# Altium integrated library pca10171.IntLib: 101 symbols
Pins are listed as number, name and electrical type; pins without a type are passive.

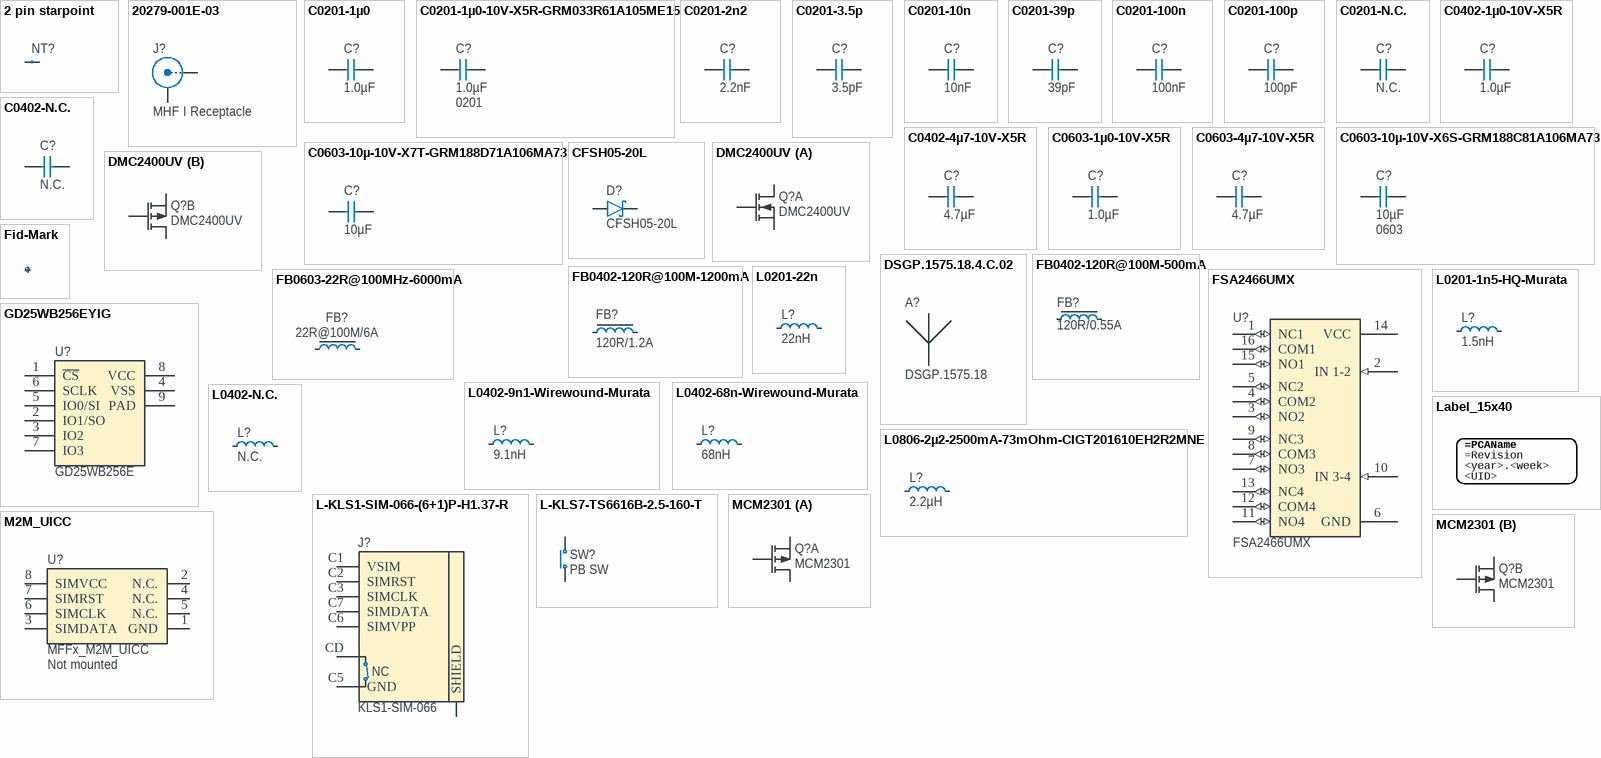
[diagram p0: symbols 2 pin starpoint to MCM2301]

## 2 pin starpoint
designator NT?, comment Net tie  (value not drawn)  (net tie, no BOM)
Starpoint; Part Number: 2 pin starpoint; Manufacturer: N.A.; Part number NEMS: 100500603; Pad Count: 2; Component Status: Active; System: Connector
footprint 2 PIN STARPOINT
pins: 1, 2

## 20279-001E-03
designator J?, comment MHF I Receptacle
Ultraminiature Coaxial Connector, 50 Ohm, SMD; Part Number: 20279-001E-03; Manufacturer: Wellshow; Part number IPS: 00000004436; Part number NEMS: 100500636; Note: N.A.; Pad Count: 3; Component Status: Active
footprint COAXIAL RF U.FL-R-SMT-1
pins: 1 X, 2 Y

## C0201-1µ0
designator C?, comment 1.0µF
Capacitor, X5R, ±10%; Part Number: C0201-1µ0; Manufacturer: N.A.; Part number IPS: 00000001723; Part number NEMS: 100200084; Note: 10V; Pad Count: 2; Component Status: Active
footprint CAPC0603X03L_C
pins: 1, 2

## C0201-1µ0-10V-X5R-GRM033R61A105ME15
designator C?, comment 1.0µF  Footprint Doc: 0201
Capacitor, X5R, ±20%, 10V; Part Number: C0201-1µ0-10V-X5R-GRM033R61A105ME15; Manufacturer: Murata; Manufacturer Part Number: GRM033R61A105ME15; Part number NEMS: 100200545; Artikkelnr Noca: N.A.; Pad Count: 2; Component Status: Active
footprint CAPC0603X03L_C
pins: 1, 2

## C0201-2n2
designator C?, comment 2.2nF
Capacitor, X7R, ±10%, 10V; Part Number: C0201-2n2; Manufacturer: N.A.; Part number IPS: 00000001778; Part number Norautron: 26470002; Part number NEMS: 100200060; Pad Count: 2; Component Status: Active
footprint CAPC0603X03L_C
pins: 1, 2

## C0201-3.5p
designator C?, comment 3.5pF
Capacitor, NP0, ±0.1pF, 25V; Part Number: C0201-3.5p; Manufacturer: Murata; Manufacturer Part Number: GJM0335C1H3R5BB01E; Part number IPS: 00000001469; Part number NEMS: 100200023; Artikkelnr Noca: N.A.; Pad Count: 2; Component Status: Active
footprint CAPC0603X03L_C
pins: 1, 2

## C0201-10n
designator C?, comment 10nF
Capacitor, X7R, ±10%; Part Number: C0201-10n; Manufacturer: N.A.; Part number IPS: 00000003480; Part number Norautron: 26621779; Part number NEMS: 100200067; Note: 10V; Pad Count: 2; Component Status: Active
footprint CAPC0603X03L_C
pins: 1, 2

## C0201-39p
designator C?, comment 39pF
Capacitor, NP0, ±1%, 25V; Part Number: C0201-39p; Manufacturer: Murata; Manufacturer Part Number: GRM0335C1E390FA01; Part number IPS: 00000001668; Part number NEMS: 100200039; Artikkelnr Noca: N.A.; Pad Count: 2; Component Status: Active
footprint CAPC0603X03L_C
pins: 1, 2

## C0201-100n
designator C?, comment 100nF
Capacitor, X5R, ±10%; Part Number: C0201-100n; Manufacturer: N.A.; Part number IPS: 00000001248, 00000002505; Part number Norautron: 262071862; Part number NEMS: 100200078; Note: 16V; Pad Count: 2; Component Status: Active
footprint CAPC0603X03L_C
pins: 1, 2

## C0201-100p
designator C?, comment 100pF
Capacitor, NP0, ±2%, 25V; Part Number: C0201-100p; Manufacturer: Murata; Manufacturer Part Number: GRM0335C1E101GA01; Part number IPS: 00000007853; Part number NEMS: 100200044; Artikkelnr Noca: N.A.; Pad Count: 2; Component Status: Active
footprint CAPC0603X03L_C
pins: 1, 2

## C0201-N.C.
designator C?, comment N.C.
Not mounted; Part Number: C0201-N.C.; Manufacturer: N.A.; Part number NEMS: 100200001; Note: Chip Cap; Assembly: Not mounted; Pad Count: 2; Component Status: Active
footprint CAPC0603X03L_C_NC
pins: 1, 2

## C0402-1µ0-10V-X5R
designator C?, comment 1.0µF
Capacitor, Ceramic, X5R, ±10%, 10V; Part Number: C0402-1µ0-10V-X5R; Manufacturer: N.A.; Part number NEMS: 100200482; Pad Count: 2; Component Status: Active
footprint CAPC1005X04L
pins: 1, 2

## C0402-4µ7-10V-X5R
designator C?, comment 4.7µF
Capacitor, X5R, 10V; Part Number: C0402-4µ7-10V-X5R; Manufacturer: Murata; Manufacturer Part Number: GRM155R61A475MEAAD; Part number NEMS: 100200415; Artikkelnr Noca: N.A.; Pad Count: 2; Component Status: Active
footprint CAPC1005X04L
pins: 1, 2

## C0402-N.C.
designator C?, comment N.C.
Not mounted; Part Number: C0402-N.C.; Manufacturer: N.A.; Part number NEMS: 100200105; Assembly: Not mounted; Note: Chip Cap; Pad Count: 2; Component Status: Active
footprint CAPC1005X04L_NC
pins: 1, 2

## C0603-1µ0-10V-X5R
designator C?, comment 1.0µF
Capacitor, Ceramic, 1.0µF 10V X5R 0603,±10%; Part Number: C0603-1µ0-10V-X5R; Manufacturer: N.A.; Part number NEMS: 100200528; Component Status: Active; Pad Count: 2
footprint CAPC1608X06L
pins: 1, 2

## C0603-4µ7-10V-X5R
designator C?, comment 4.7µF
Capacitor, Ceramic, X5R, ±10%, 10V; Part Number: C0603-4µ7-10V-X5R; Manufacturer: N.A.; Part number Norautron: 262081761; Part number NEMS: 100200479; Pad Count: 2; Component Status: Active
footprint CAPC1608X06L
pins: 1, 2

## C0603-10µ-10V-X6S-GRM188C81A106MA73
designator C?, comment 10µF  Footprint Doc: 0603
Capacitor, Ceramic, 10µF 10V X6S 0603,±20%; Part Number: C0603-10µ-10V-X6S-GRM188C81A106MA73; Manufacturer: Murata; Manufacturer Part Number: GRM188C81A106MA73; Part number NEMS: 100200520; Component Status: Active; Pad Count: 2; Artikkelnr Noca: N.A.
footprint CAPC1608X06L
pins: 1, 2

## C0603-10µ-10V-X7T-GRM188D71A106MA73
designator C?, comment 10µF
Capacitor, X7T, ±20%, 10V; Part Number: C0603-10µ-10V-X7T-GRM188D71A106MA73; Manufacturer: Murata; Manufacturer Part Number: GRM188D71A106MA73; Part number IPS: 00000004696; Part number NEMS: 100200414; Component Status: Active; Pad Count: 2; Note: 10VDC; Artikkelnr Noca: N.A.
footprint CAPC1608X06L
pins: 1, 2

## CFSH05-20L
designator D?
DIODE SCHOTTKY 20V 500MA SOD882; Manufacturer: Central Semiconductor Corp.; Part number IPS: 00000002493; Part number NEMS: 101300101; Note: N.A.; Pad Count: 2; Component Status: Active
footprint SODFL35X40-2N
pins: 1 A, 3 C

## DMC2400UV
designator Q?
Dual N & P Ch MOFET, 1.03A/0.7A, 480mOhm, 450mW; Manufacturer: Diodes Incorporated; Part number IPS: 00000007803; Part number NEMS: 101300117; Note: Dual N & P Channel Digital FET; Artikkelnr Noca: N.A.; Pad Count: 6; Component Status: Active
footprint SOTFL50P162X60-6N
part A pins: 1 S1, 2 G1, 6 D1
part B pins: 3 D2, 4 S2, 5 G2

## DSGP.1575.18.4.C.02
designator A?, comment DSGP.1575.18
18 x 18 mm Low Profile GPS L1 / GALILEO E1 Passive Patch Antenna; Part Number: DSGP.1575.18.4.C.02; Manufacturer: Taoglas; Part number IPS: 00000007687; Part number NEMS: 100700073; Note: N.A.; Pad Count: 2; Component Status: Active
footprint DSGP.1575.18.4.C.02
pins: 1, 2 GND (power) hidden to GND

## FB0402-120R@100M-500mA
designator FB?, comment 120R/0.55A
Ferrite Bead, 120 Ohm @ 100MHz, 500mA, 250 mOhm Max; Part Number: FB0402-120R@100M-500mA; Manufacturer: Murata; Manufacturer Part Number: BLM15AG121SN1D; Part number IPS: 00000009954; Part number Norautron: 265230631; Part number NEMS: 100300099; Note: Chip EMIFIL Inductor Type Chip Ferrite Bead; Artikkelnr Noca: 33029317; Pad Count: 2; Component Status: Active
footprint INDC1005X04L
pins: 1, 2

## FB0402-120R@100M-1200mA
designator FB?, comment 120R/1.2A
Ferrite Bead, 120 Ohm @ 100MHz, 1200mA, 75 mOhm Max; Part Number: FB0402-120R@100M-1200mA; Manufacturer: Murata; Manufacturer Part Number: BLM15EX121SN1; Part number NEMS: 100300416; Component Status: Active; Pad Count: 2; Note: N.A.
footprint INDC1005X04L
pins: 1, 2

## FB0603-22R@100MHz-6000mA
designator FB?, comment 22R@100M/6A
Ferrite Bead, 22 Ohm @ 100MHz, 6000mA, 8 mOhm Max; Part Number: FB0603-22R@100MHz-6000mA; Manufacturer: Murata; Manufacturer Part Number: BLM18SD220SN1D; Component Status: Active; Pad Count: 2; Note: Chip EMIFIL Inductor Type Chip Ferrite Bead; Artikkelnr Noca: N.A.
footprint INDC1608X06L
pins: 1, 2

## Fid-Mark
designator Fid?, comment Fiducial mark  (value not drawn)  (no BOM)
Part Number: Fid-Mark; Manufacturer: N.A.; Part number NEMS: 100500073; Value: N.A.; Assembly: Not mounted; Pad Count: 1; Component Status: Active; System: Connector
footprint Fiducial

## FSA2466UMX
designator U?
Data / Audio Low-Voltage Dual DPDT Analog Switch; Manufacturer: ON Semiconductor; Part number IPS: 00000009986; Part number Norautron: 26500608; Part number NEMS: 101900422; Note: N.A.; Artikkelnr Noca: 15070069; Pad Count: 16; Component Status: Active
footprint XQFN40P180X260X50-16N
pins: 1 NC1 (io), 2 IN 1-2 (in), 3 NO2 (io), 4 COM2 (io), 5 NC2 (io), 6 GND (power), 7 NO3 (io), 8 COM3 (io), 9 NC3 (io), 10 IN 3-4 (in), 11 NO4 (io), 12 COM4 (io), 13 NC4 (io), 14 VCC (power), 15 NO1 (io), 16 COM1 (io)
1 alternate drawing of the same symbol

## GD25WB256EYIG
designator U?, comment GD25WB256E
Quad Serial Flash, 256Mbit, 104MHz, 1.65V - 3.6V; Part Number: GD25WB256EYIG; Manufacturer: GigaDevice; Part number NEMS: 101900774; Note: N.A.; Pad Count: 8; Component Status: Active
footprint SON127P800X80_HS-9N
pins: 1 ~{CS}, 2 IO1/SO, 3 IO2, 4 VSS, 5 IO0/SI, 6 SCLK, 7 IO3, 8 VCC, 9 PAD

## L0201-1n5-HQ-Murata
designator L?, comment 1.5nH
Inductor, 1000mA, ±0.1ｎH, 50mOhm; Part Number: L0201-1n5-HQ-Murata; Manufacturer: Murata; Manufacturer Part Number: LQP03HQ1N5B02; Part number NEMS: 100300202; Note: -55°C ~ 125°C; Artikkelnr Noca: N.A.; Pad Count: 2; Component Status: Active
footprint INDC0603X03L_C
pins: 1, 2

## L0201-22n
designator L?, comment 22nH
Chip Inductor; Part Number: L0201-22n; Manufacturer: N.A.; Part number IPS: 00000001478; Part number NEMS: 100300034; Note: High frequency chip inductor ±10%; Pad Count: 2; Component Status: Active
footprint INDC0603X03L_C
pins: 1, 2

## L0402-9n1-Wirewound-Murata
designator L?, comment 9.1nH
Inductor, 540mA, ±2%, 140mΩ, Q=25; Part Number: L0402-9n1-Wirewound-Murata; Manufacturer: Murata; Manufacturer Part Number: LQW15AN9N1G00; Part number IPS: 00000002497; Part number NEMS: 100300357; Note: -55°C ~ 125°C; Artikkelnr Noca: N.A.; Pad Count: 2; Component Status: Active
footprint INDC1005X04L_WW
pins: 1, 2

## L0402-68n-Wirewound-Murata
designator L?, comment 68nH
Inductor, 140mA, ±2%, 1960mΩ, Q=20; Part Number: L0402-68n-Wirewound-Murata; Manufacturer: Murata; Manufacturer Part Number: LQW15AN68NG00; Part number IPS: 00000002494; Part number NEMS: 100300389; Note: -55°C ~ 125°C; Artikkelnr Noca: N.A.; Pad Count: 2; Component Status: Active
footprint INDC1005X04L_WW
pins: 1, 2

## L0402-N.C.
designator L?, comment N.C.
Not mounted; Part Number: L0402-N.C.; Manufacturer: N.A.; Part number NEMS: 100300037; Assembly: Not mounted; Pad Count: 2; Component Status: Active
footprint INDC1005X04L_NC
pins: 1, 2

## L0806-2µ2-2500mA-73mOhm-CIGT201610EH2R2MNE
designator L?, comment 2.2µH
Inductor, Irms=2.5A, Isat=2.9A, ±20%, DCR=73mΩ; Part Number: L0806-2µ2-2500mA-73mOhm-CIGT201610EH2R2MNE; Manufacturer: Samsung Electro-Mechanics America; Manufacturer Part Number: CIGT201610EH2R2MNE; Part number Norautron: 26521789; Part number NEMS: 100300400; Component Status: Active; Pad Count: 2; Note: Unshielded Thin Film Inductor; Artikkelnr Noca: N.A.
footprint INDC2016X10N
pins: 1, 2

## L-KLS1-SIM-066-(6+1)P-H1.37-R
designator J?, comment KLS1-SIM-066
Nano SIM Card Connector, Push-Push, 6-Pin, H1.37mm, with CD Pin; Part Number: L-KLS1-SIM-066-(6+1)P-H1.37-R; Manufacturer: KLS Electronic; Part number NEMS: 100500776; Note: N.A.; Pad Count: 7; Component Status: Active
footprint KLS1-SIM-066
pins: 0 SHIELD (power), C1 VSIM, C2 SIMRST, C3 SIMCLK, C5 GND, C6 SIMVPP, C7 SIMDATA, CD

## L-KLS7-TS6616B-2.5-160-T
designator SW?, comment PB SW
Tactile Switch, SPNO, SMD, 160gf, 6.2x6.4x2.5mm; Part Number: L-KLS7-TS6616B-2.5-160-T; Manufacturer: KLS; Part number NEMS: 101500133, 101500001; Note: N.A.; Pad Count: 4; Component Status: Active
footprint L-KLS7-TS6616B-2.5-160-T
pins: 1 N.O, 2 COM

## Label_15x40
designator LABEL?, comment 15x40mm  (value not drawn)
PCA version label, stick-on, 15x40mm; Part Number: Label_15x40; Manufacturer: Ellco Etikett; Manufacturer Part Number: 51945; Part number NEMS: 101200030; Component Status: Active; Pad Count: 0; Note: N.A.; Assembly: Not mounted
footprint LabelSilk_15x40

## M2M_UICC
designator U?, comment MFFx_M2M_UICC  Assembly: Not mounted
M2M UICC SIM Card; Manufacturer: N.A.; Part number NEMS: 101900595; Pad Count: 8; Component Status: Active
footprint SON127P600X90_HS-8N
pins: 1 GND, 2 N.C., 3 SIMDATA, 4 N.C., 5 N.C., 6 SIMCLK, 7 SIMRST, 8 SIMVCC

## MCM2301
designator Q?
Dual P-Channel MOFET, 3.8A, 90mOhm max, 1.4W; Manufacturer: Micro Commercial Components; Part number NEMS: 101300199; Note: N.A.; Pad Count: 6; Component Status: Active
footprint DFN65P200X200X80_HS-6N
part A pins: 1 S1, 2 G1, 6 D1
part B pins: 3 D2, 4 S2, 5 G2

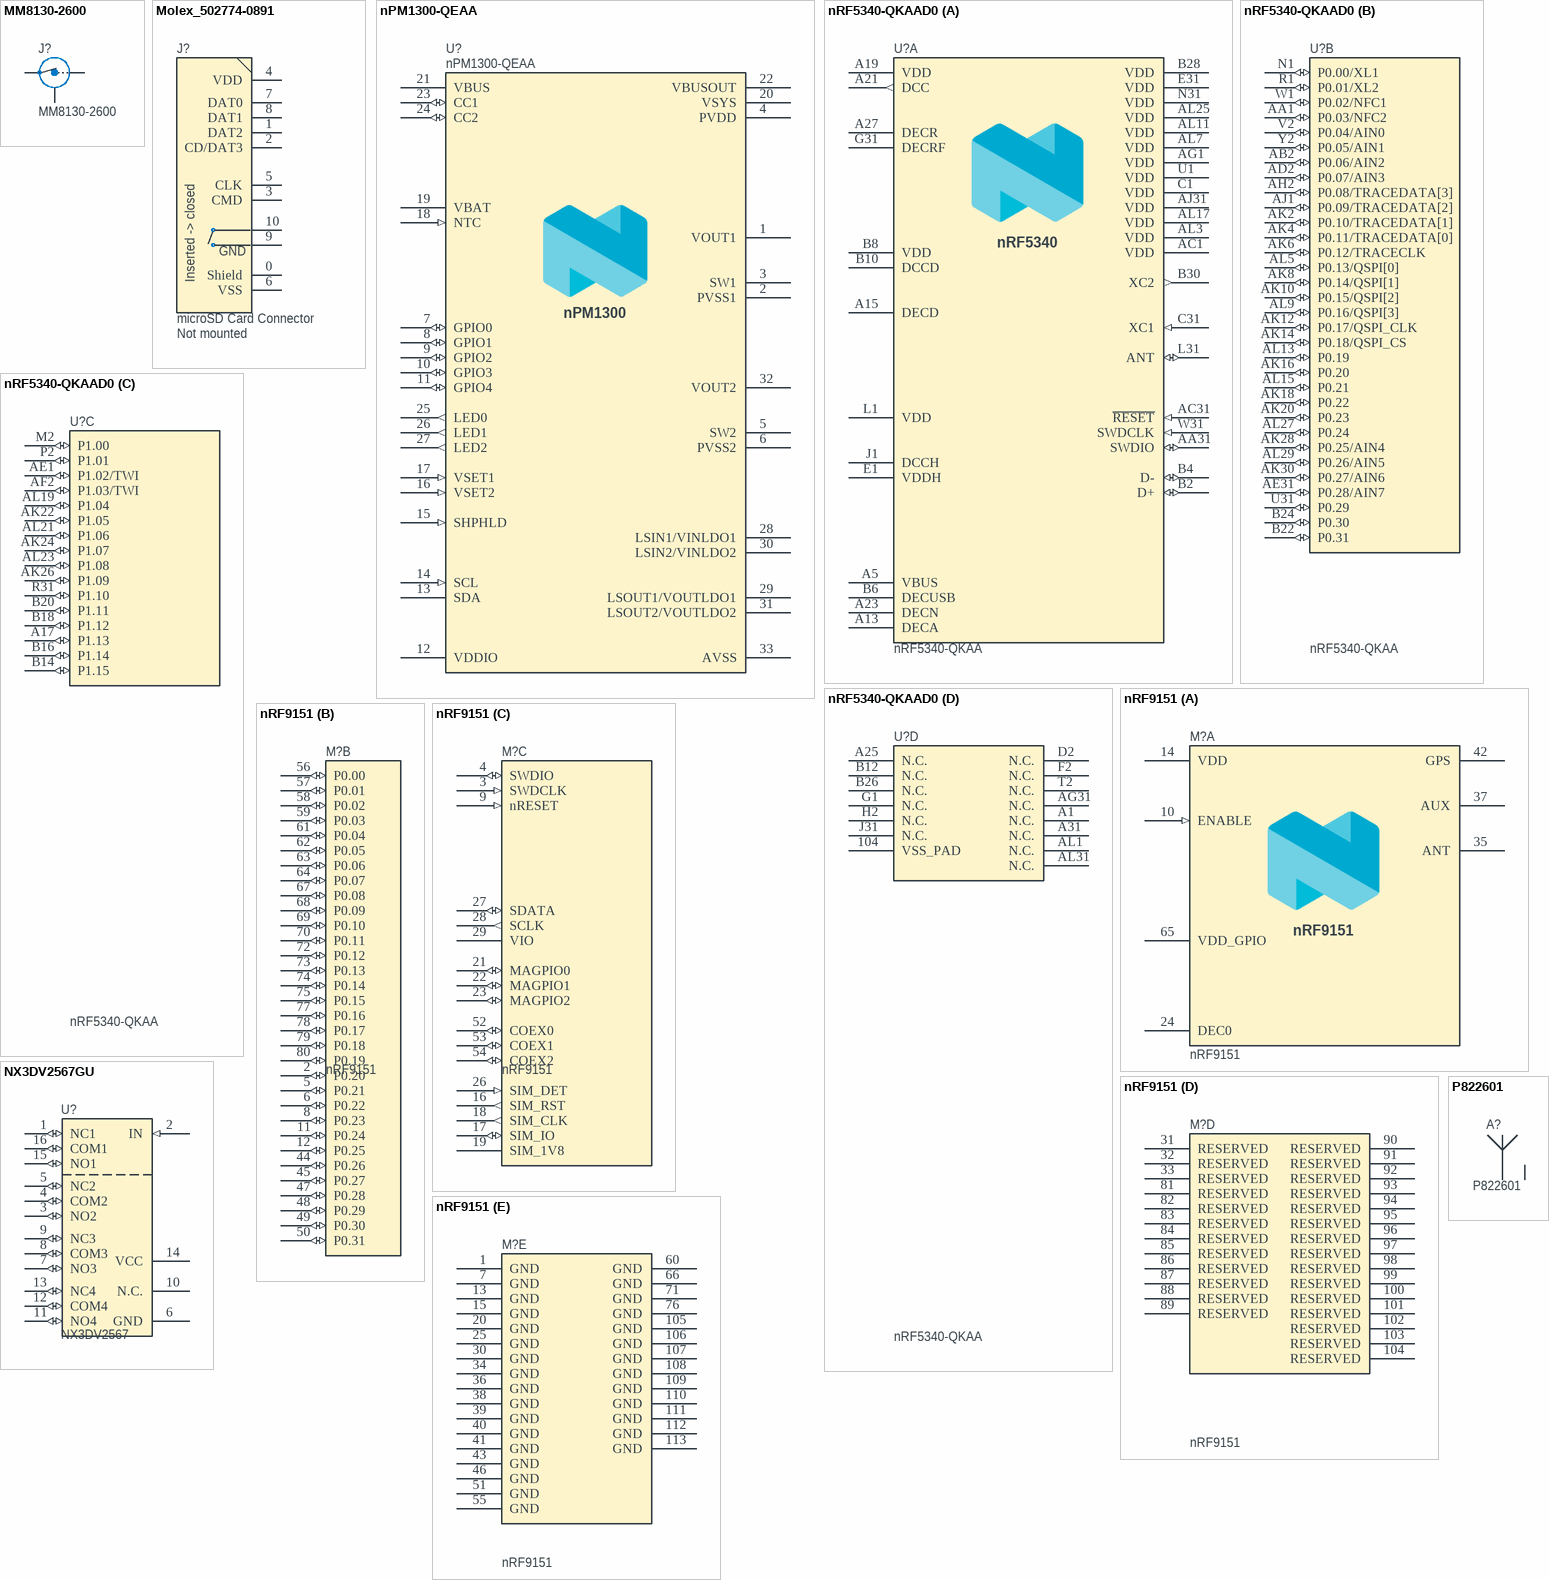
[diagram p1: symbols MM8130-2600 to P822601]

## MM8130-2600
designator J?
Coaxial Connector with Switch; Manufacturer: Murata; Part number IPS: 00000009955; Part number Norautron: 26030338; Part number NEMS: 100500400; Note: N.A.; Artikkelnr Noca: 55029011; Pad Count: 3; Component Status: Active
footprint COAXIAL-SWF
pins: 1 IN, 2 Shield, 3 OUT

## Molex_502774-0891
designator J?, comment microSD Card Connector  Assembly: Not mounted
1.10mm Pitch microSD Memory Card Connector, Reverse Mount Surface Mount, Push-Push Type; Part Number: Molex_502774-0891; Manufacturer: Molex; Manufacturer Part Number: 502774-0891; Part number IPS: 00000001284; Part number NEMS: 100500509; Note: N.A.; Pad Count: 14; Component Status: Active
footprint Molex_502774-0891
pins: 0 Shield, 1 DAT2, 2 CD/DAT3, 3 CMD, 4 VDD (power), 5 CLK, 6 VSS (power), 7 DAT0, 8 DAT1, 9, 10

## nPM1300-QEAA
designator U?
Li-Ion/Li-Polymer USB-C battery charger with high efficiency buck regulators, LDOs or load switches, LED drivers, TWI and VBUSOUT; Manufacturer: Nordic Semiconductor; Part number NEMS: 102000291; Component Status: Active; Pad Count: 33; Note: N.A.
footprint Nordic_QFN50P500X500X90-33N
pins: 1 VOUT1 (power), 2 PVSS1 (power), 3 SW1 (power), 4 PVDD (power), 5 SW2 (power), 6 PVSS2 (power), 7 GPIO0 (io), 8 GPIO1 (io), 9 GPIO2 (io), 10 GPIO3 (io), 11 GPIO4 (io), 12 VDDIO (power), 13 SDA (oc), 14 SCL (in), 15 SHPHLD (in), 16 VSET2 (in), 17 VSET1 (in), 18 NTC (in), 19 VBAT, 20 VSYS (power), 21 VBUS (power), 22 VBUSOUT (power), 23 CC1 (io), 24 CC2 (io), 25 LED0 (out), 26 LED1 (out), 27 LED2 (out), 28 LSIN1/VINLDO1 (power), 29 LSOUT1/VOUTLDO1 (power), 30 LSIN2/VINLDO2 (power), 31 LSOUT2/VOUTLDO2 (power), 32 VOUT2 (power), 33 AVSS (power)

## nRF5340-QKAAD0
designator U?, comment nRF5340-QKAA
Multi-protocol Bluetooth Low Energy, IEEE 802.15.4, ANT and 2.4GHz proprietary system-on-chip; Part Number: nRF5340-QKAAD0; Manufacturer: Nordic Semiconductor; Part number Norautron: NOD26470035; Part number NEMS: 102000216; Pad Count: 98; Note: N.A.; Component Status: Active
footprint AQFN40P700X700X85_HS-99N
part A pins: A5 VBUS (power), A13 DECA (power), A15 DECD (power), A19 VDD (power), A21 DCC (out), A23 DECN (power), A27 DECR (power), AA31 SWDIO (io), AC1 VDD (power), AC31 ~{RESET} (in), AG1 VDD (power), AJ31 VDD (power), AL3 VDD (power), AL7 VDD (power), AL11 VDD (power), AL17 VDD (power), AL25 VDD (power), B2 D+ (io), B4 D- (io), B6 DECUSB (power), B8 VDD (power), B10 DCCD (power), B28 VDD (power), B30 XC2 (out), C1 VDD (power), C31 XC1 (in), E1 VDDH (power), E31 VDD (power), G31 DECRF (power), J1 DCCH (power), L1 VDD (power), L31 ANT (io), N31 VDD (power), U1 VDD (power), W31 SWDCLK (in)
part B pins: AA1 P0.03/NFC2 (io), AB2 P0.06/AIN2 (io), AD2 P0.07/AIN3 (io), AE31 P0.28/AIN7 (io), AH2 P0.08/TRACEDATA[3] (io), AJ1 P0.09/TRACEDATA[2] (io), AK2 P0.10/TRACEDATA[1] (io), AK4 P0.11/TRACEDATA[0] (io), AK6 P0.12/TRACECLK (io), AK8 P0.14/QSPI[1] (io), AK10 P0.15/QSPI[2] (io), AK12 P0.17/QSPI_CLK (io), AK14 P0.18/QSPI_CS (io), AK16 P0.20 (io), AK18 P0.22 (io), AK20 P0.23 (io), AK28 P0.25/AIN4 (io), AK30 P0.27/AIN6 (io), AL5 P0.13/QSPI[0] (io), AL9 P0.16/QSPI[3] (io), AL13 P0.19 (io), AL15 P0.21 (io), AL27 P0.24 (io), AL29 P0.26/AIN5 (io), B22 P0.31 (io), B24 P0.30 (io), N1 P0.00/XL1 (io), R1 P0.01/XL2 (io), U31 P0.29 (io), V2 P0.04/AIN0 (io), W1 P0.02/NFC1 (io), Y2 P0.05/AIN1 (io)
part C pins: A17 P1.13 (io), AE1 P1.02/TWI (io), AF2 P1.03/TWI (io), AK22 P1.05 (io), AK24 P1.07 (io), AK26 P1.09 (io), AL19 P1.04 (io), AL21 P1.06 (io), AL23 P1.08 (io), B14 P1.15 (io), B16 P1.14 (io), B18 P1.12 (io), B20 P1.11 (io), M2 P1.00 (io), P2 P1.01 (io), R31 P1.10 (io)
part D pins: 104 VSS_PAD (power), A1 N.C., A25 N.C., A31 N.C., AG31 N.C., AL1 N.C., AL31 N.C., B12 N.C., B26 N.C., D2 N.C., F2 N.C., G1 N.C., H2 N.C., J31 N.C., T2 N.C.

## nRF9151
designator M?
Low power System-in-Package with integrated LTE-M/NB-IoT modem and GPS; Manufacturer: Nordic Semiconductor; Part number NEMS: 102000307; Component Status: Active; Pad Count: 113; Note: N.A.
footprint LGA50P1210X1110X130-113N
part A pins: 10 ENABLE (in), 14 VDD (power), 24 DEC0, 35 ANT, 37 AUX, 42 GPS, 65 VDD_GPIO (power)
part B pins: 2 P0.20 (io), 5 P0.21 (io), 6 P0.22 (io), 8 P0.23 (io), 11 P0.24 (io), 12 P0.25 (io), 44 P0.26 (io), 45 P0.27 (io), 47 P0.28 (io), 48 P0.29 (io), 49 P0.30 (io), 50 P0.31 (io), 56 P0.00 (io), 57 P0.01 (io), 58 P0.02 (io), 59 P0.03 (io), 61 P0.04 (io), 62 P0.05 (io), 63 P0.06 (io), 64 P0.07 (io), 67 P0.08 (io), 68 P0.09 (io), 69 P0.10 (io), 70 P0.11 (io), 72 P0.12 (io), 73 P0.13 (io), 74 P0.14 (io), 75 P0.15 (io), 77 P0.16 (io), 78 P0.17 (io), 79 P0.18 (io), 80 P0.19 (io)
part C pins: 3 SWDCLK (in), 4 SWDIO (io), 9 nRESET (in), 16 SIM_RST (out), 17 SIM_IO (io), 18 SIM_CLK (out), 19 SIM_1V8 (power), 21 MAGPIO0 (io), 22 MAGPIO1 (io), 23 MAGPIO2 (io), 26 SIM_DET (in), 27 SDATA (io), 28 SCLK (out), 29 VIO, 52 COEX0 (io), 53 COEX1 (io), 54 COEX2 (io)
part D pins: 31 RESERVED, 32 RESERVED, 33 RESERVED, 81 RESERVED, 82 RESERVED, 83 RESERVED, 84 RESERVED, 85 RESERVED, 86 RESERVED, 87 RESERVED, 88 RESERVED, 89 RESERVED, 90 RESERVED, 91 RESERVED, 92 RESERVED, 93 RESERVED, 94 RESERVED, 95 RESERVED, 96 RESERVED, 97 RESERVED, 98 RESERVED, 99 RESERVED, 100 RESERVED, 101 RESERVED, 102 RESERVED, 103 RESERVED, 104 RESERVED
part E pins: 1 GND, 7 GND, 13 GND, 15 GND, 20 GND, 25 GND, 30 GND, 34 GND, 36 GND, 38 GND, 39 GND, 40 GND, 41 GND, 43 GND, 46 GND, 51 GND, 55 GND, 60 GND, 66 GND, 71 GND, 76 GND, 105 GND, 106 GND, 107 GND, 108 GND, 109 GND, 110 GND, 111 GND, 112 GND, 113 GND

## NX3DV2567GU
designator U?, comment NX3DV2567
Low-ohmic four-pole double-throw analog switch; Part Number: NX3DV2567GU; Manufacturer: NXP Semiconductors; Part number IPS: 00000007816; Part number NEMS: 101900290; Note: N.A.; Artikkelnr Noca: 15079317; Pad Count: 16; Component Status: Active
footprint XQFN40P180X260X50-16N
pins: 1 NC1 (io), 2 IN (in), 3 NO2 (io), 4 COM2 (io), 5 NC2 (io), 6 GND (power), 7 NO3 (io), 8 COM3 (io), 9 NC3 (io), 10 N.C., 11 NO4 (io), 12 COM4 (io), 13 NC4 (io), 14 VCC (power), 15 NO1 (io), 16 COM1 (io)
3 alternate drawings of the same symbol

## P822601
designator A?
ANTENNA PRESTTA OCTABAND LTE; Manufacturer: Ethertronics; Part number IPS: 00000009001; Part number NEMS: 100700043; Note: N.A.; Pad Count: 2; Component Status: Active
footprint P822601
pins: 1, 2

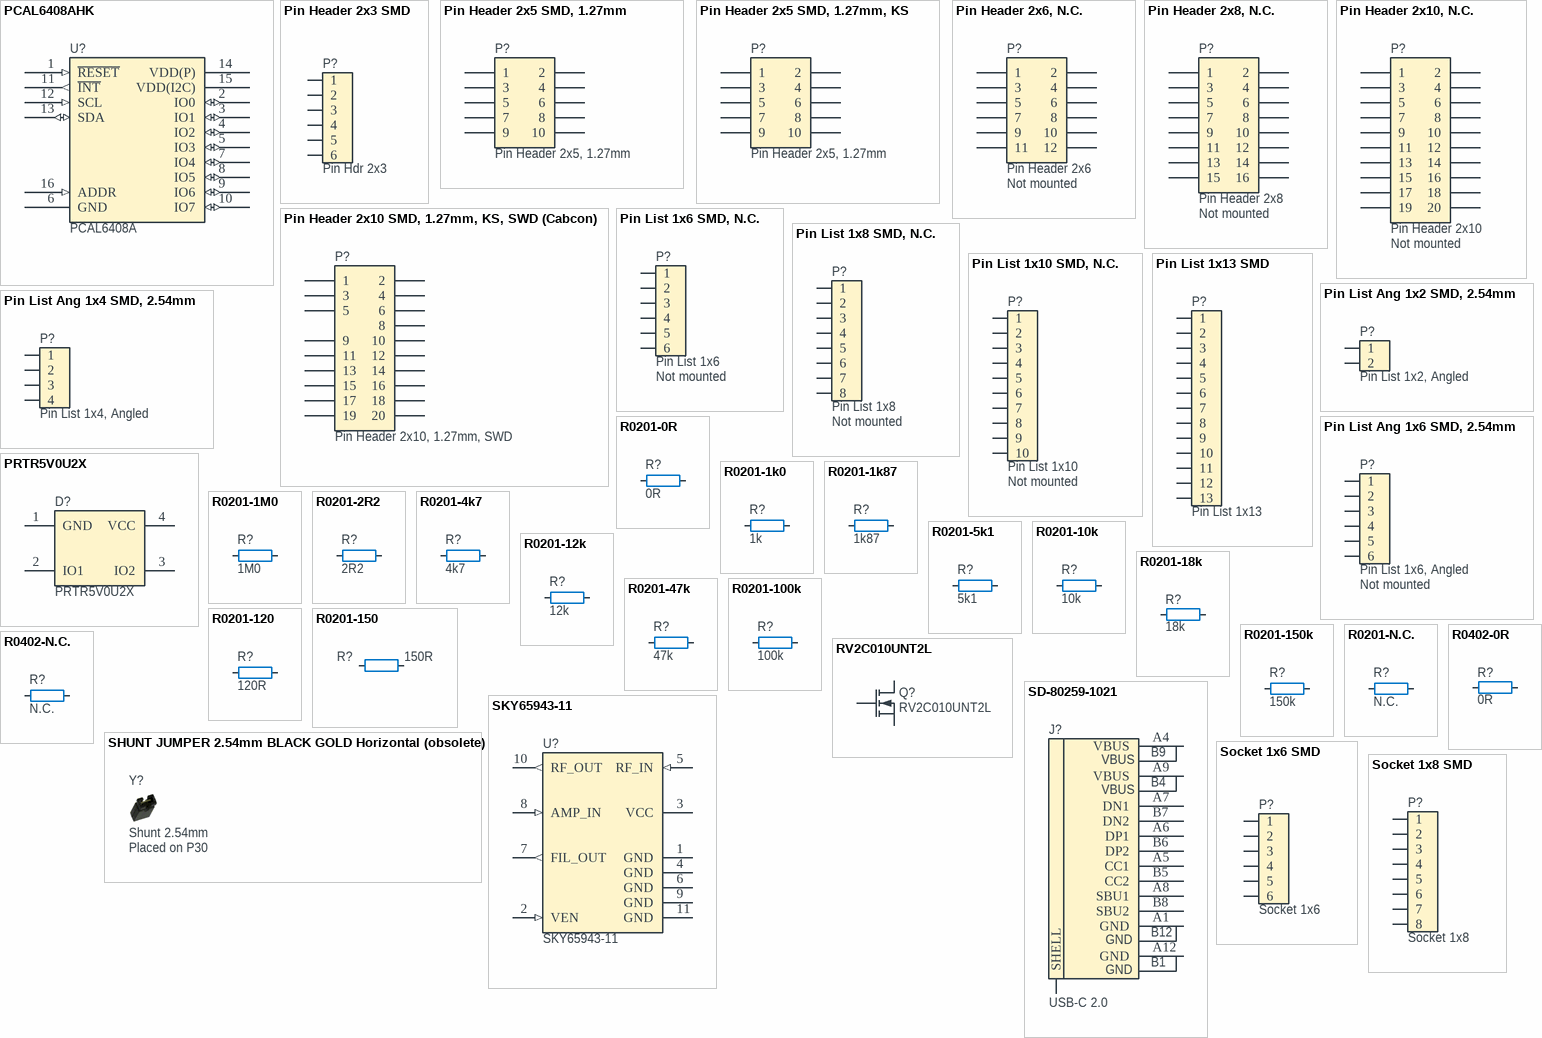
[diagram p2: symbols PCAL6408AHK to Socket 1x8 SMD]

## PCAL6408AHK
designator U?, comment PCAL6408A
8-bit I2C-bus I/O expander with interrupt output; Part Number: PCAL6408AHK; Manufacturer: NXP Semiconductors; Part number IPS: 00000009987; Part number NEMS: 101900289; Note: N.A.; Artikkelnr Noca: 15079321; Pad Count: 16; Component Status: Active
footprint XQFN40P180X260X50-16N
pins: 1 ~{RESET} (in), 2 IO0 (io), 3 IO1 (io), 4 IO2 (io), 5 IO3 (io), 6 GND (power), 7 IO4 (io), 8 IO5 (io), 9 IO6 (io), 10 IO7 (io), 11 ~{INT} (out), 12 SCL (in), 13 SDA (io), 14 VDD(P) (power) "VDD 2.3V - 5.5V", 15 VDD(I2C) (power), 16 ADDR (in)

## Pin Header 2x3 SMD
designator P?, comment Pin Hdr 2x3
Pin Header 2x3, 2.54mm (100mil) SMD; Part Number: Pin Header 2x3 SMD; Manufacturer: WCON; Manufacturer Part Number: 1125-1203S0M116R1; Part number IPS: 00000009966; Part number Norautron: N.A.; Part number NEMS: 100500242; Artikkelnr Noca: 55010007; Pad Count: 6; Component Status: Active; System: Connector
footprint HDR_2x3-SMD
pins: 1, 2, 3, 4, 5, 6
1 alternate drawing of the same symbol

## Pin Header 2x5 SMD, 1.27mm
designator P?, comment Pin Header 2x5, 1.27mm
Pin Header 2x5, 1.27mm (50mil), SMD; Part Number: Pin Header 2x5 SMD, 1.27mm; Manufacturer: WCON; Manufacturer Part Number: 1325-1205S0M078R1; Part number IPS: 00000009970; Part number NEMS: 100500259; Note: N.A.; Artikkelnr Noca: 55019196; Pad Count: 10; Component Status: Active; System: Connector
footprint HDR_2x5-SMD-1.27mm
pins: 1, 2, 3, 4, 5, 6, 7, 8, 9, 10

## Pin Header 2x5 SMD, 1.27mm, KS
designator P?, comment Pin Header 2x5, 1.27mm
Pin Header 2x5, 1.27mm (50mil), SMD, Keying Shroud; Part Number: Pin Header 2x5 SMD, 1.27mm, KS; Manufacturer: WCON; Manufacturer Part Number: 3132-10MS0BK00R1; Part number IPS: 00000009968; Part number NEMS: 100500261; Note: N.A.; Artikkelnr Noca: 55010009; Pad Count: 10; Component Status: Active; System: Connector
footprint HDR_2x5-SMD-1.27mm-K
pins: 1, 2, 3, 4, 5, 6, 7, 8, 9, 10

## Pin Header 2x6, N.C.
designator P?, comment Pin Header 2x6  Assembly: Not mounted
Pin Header 2x6, 2.54mm (100mil); Part Number: Pin Header 2x6, N.C.; Manufacturer: N.A.; Part number NEMS: 100500265; Pad Count: 12; Component Status: Active; System: Connector
footprint HDR_2x6-NC
pins: 1, 2, 3, 4, 5, 6, 7, 8, 9, 10, 11, 12

## Pin Header 2x8, N.C.
designator P?, comment Pin Header 2x8  Assembly: Not mounted
Pin Header 2x8, 2.54mm (100mil); Part Number: Pin Header 2x8, N.C.; Manufacturer: N.A.; Part number NEMS: 100500270; Pad Count: 16; Component Status: Active; System: Connector
footprint HDR_2x8-NC
pins: 1, 2, 3, 4, 5, 6, 7, 8, 9, 10, 11, 12, 13, 14, 15, 16
1 alternate drawing of the same symbol

## Pin Header 2x10 SMD, 1.27mm, KS, SWD (Cabcon)
designator P?, comment Pin Header 2x10, 1.27mm, SWD
Pin Header 2x10, 1.27mm (50mil), SMD, Keying Shroud, Removed Pin 7; Part Number: Pin Header 2x10 SMD, 1.27mm, KS, SWD (Cabcon); Manufacturer: WCON; Manufacturer Part Number: 3132-20MS0BK00R3; Part number NEMS: 100500841,100500280; Note: N.A.; Pad Count: 19; Component Status: Active; System: Connector
footprint HDR_2x10-SMD-1.27mm-K-SWD
pins: 1, 2, 3, 4, 5, 6, 8, 9, 10, 11, 12, 13, 14, 15, 16, 17, 18, 19, 20

## Pin Header 2x10, N.C.
designator P?, comment Pin Header 2x10  Assembly: Not mounted
Pin Header 2x10, 2.54mm (100mil); Part Number: Pin Header 2x10, N.C.; Manufacturer: N.A.; Part number NEMS: 100500274; Pad Count: 20; Component Status: Active; System: Connector
footprint HDR_2x10-NC
pins: 1, 2, 3, 4, 5, 6, 7, 8, 9, 10, 11, 12, 13, 14, 15, 16, 17, 18, 19, 20

## Pin List 1x6 SMD, N.C.
designator P?, comment Pin List 1x6  Assembly: Not mounted
Pin List 1x6, 2.54mm (100mil), SMD; Part Number: Pin List 1x6 SMD, N.C.; Manufacturer: WCON; Manufacturer Part Number: 1125-1106S0M116R2; Part number NEMS: 100500321; Note: N.A.; Artikkelnr Noca: 55010026; Pad Count: 6; Component Status: Active; System: Connector
footprint LIST_1x6_SMD-NC
pins: 1, 2, 3, 4, 5, 6
1 alternate drawing of the same symbol

## Pin List 1x8 SMD, N.C.
designator P?, comment Pin List 1x8  Assembly: Not mounted
Pin List 1x8, 2.54mm (100mil), SMD; Part Number: Pin List 1x8 SMD, N.C.; Manufacturer: WCON; Manufacturer Part Number: 1125-1108S0M116R2; Part number NEMS: 100500330; Note: N.A.; Artikkelnr Noca: 55010006; Pad Count: 8; Component Status: Active; System: Connector
footprint LIST_1x8_SMD-NC
pins: 1, 2, 3, 4, 5, 6, 7, 8
1 alternate drawing of the same symbol

## Pin List 1x10 SMD, N.C.
designator P?, comment Pin List 1x10  Assembly: Not mounted
Pin List 1x10, 2.54mm (100mil), SMD; Part Number: Pin List 1x10 SMD, N.C.; Manufacturer: WCON; Manufacturer Part Number: 1125-1110S0M116R2; Part number NEMS: 100500338; Note: N.A.; Artikkelnr Noca: 55010028; Pad Count: 10; Component Status: Active; System: Connector
footprint LIST_1x10_SMD-NC
pins: 1, 2, 3, 4, 5, 6, 7, 8, 9, 10
1 alternate drawing of the same symbol

## Pin List 1x13 SMD
designator P?, comment Pin List 1x13
Pin List 1x13, 2.54mm (100mil), SMD; Part Number: Pin List 1x13 SMD; Manufacturer: N.A.; Part number IPS: 00000002499; Part number NEMS: 100500345; Pad Count: 13; Component Status: Active; System: Connector
footprint LIST_1x13_SMD
pins: 1, 2, 3, 4, 5, 6, 7, 8, 9, 10, 11, 12, 13

## Pin List Ang 1x2 SMD, 2.54mm
designator P?, comment Pin List 1x2, Angled
Pin List 1x2, 2.54mm (100mil), Right Angled, SMD; Part Number: Pin List Ang 1x2 SMD, 2.54mm; Manufacturer: WCON; Manufacturer Part Number: 1125B-1102S0Z135R2; Part number IPS: 00000009972; Part number NEMS: 100500354; Note: N.A.; Artikkelnr Noca: 55010023; Pad Count: 2; Component Status: Active; System: Connector
footprint LIST_ANG_1x2-SMD-2.54MM
pins: 1, 2

## Pin List Ang 1x4 SMD, 2.54mm
designator P?, comment Pin List 1x4, Angled
Pin List 1x4, 2.54mm (100mil), Right Angled, SMD; Part Number: Pin List Ang 1x4 SMD, 2.54mm; Manufacturer: WCON; Manufacturer Part Number: 1125B-1104S0Z135CR02; Part number IPS: 00000004780; Part number NEMS: 100500358; Note: N.A.; Pad Count: 4; Component Status: Active; System: Connector
footprint LIST_ANG_1x4-SMD-2.54MM
pins: 1, 2, 3, 4
1 alternate drawing of the same symbol

## Pin List Ang 1x6 SMD, 2.54mm
designator P?, comment Pin List 1x6, Angled  Assembly: Not mounted
Pin List 1x6, 2.54mm (100mil), Right Angled, SMD; Part Number: Pin List Ang 1x6 SMD, 2.54mm; Manufacturer: N.A.; Part number IPS: 00000003922; Part number NEMS: 100500362; Pad Count: 6; Component Status: Active; System: Connector
footprint LIST_ANG_1x6-SMD-2.54MM
pins: 1, 2, 3, 4, 5, 6
1 alternate drawing of the same symbol

## PRTR5V0U2X
designator D?
Ultra low capacitance double rail-to-rail ESD protection diode; Manufacturer: NXP Semiconductors; Part number IPS: 00000009951; Part number Norautron: 26313940; Part number NEMS: 101300082; Note: N.A.; Artikkelnr Noca: 10069015; Pad Count: 4; Component Status: Active
footprint SOT190P230X110-4L
pins: 1 GND, 2 IO1, 3 IO2, 4 VCC

## R0201-0R
designator R?, comment 0R
Resistor, ±5%, 0.05W; Part Number: R0201-0R; Manufacturer: N.A.; Part number IPS: 00000003245; Part number NEMS: 100100001; Note: Chip Res 5%; Pad Count: 2; Component Status: Active
footprint RESC0603X03L_C
pins: 1, 2

## R0201-1k0
designator R?, comment 1k
Resistor, ±1%, 0.05W; Part Number: R0201-1k0; Manufacturer: N.A.; Part number IPS: 00000005786; Part number NEMS: 100100043; Note: Chip Res 1%; Pad Count: 2; Component Status: Active
footprint RESC0603X03L_C
pins: 1, 2

## R0201-1k87
designator R?, comment 1k87
Resistor, ±1%, 0.05W; Part Number: R0201-1k87; Manufacturer: N.A.; Part number NEMS: 100100050; Note: Chip Res 1%; Pad Count: 2; Component Status: Active
footprint RESC0603X03L_C
pins: 1, 2

## R0201-1M0
designator R?, comment 1M0
Resistor, ±1%, 0.05W; Part Number: R0201-1M0; Manufacturer: N.A.; Part number IPS: 00000001418; Part number Norautron: 26107108; Part number NEMS: 100100093; Note: Chip Res 1%; Pad Count: 2; Component Status: Active
footprint RESC0603X03L_C
pins: 1, 2

## R0201-2R2
designator R?, comment 2R2
Resistor, ±1%, 0.05W; Part Number: R0201-2R2; Manufacturer: N.A.; Part number Norautron: 26470029; Part number NEMS: 100100006; Pad Count: 2; Note: Chip Res 1%; Component Status: Active
footprint RESC0603X03L_C
pins: 1, 2

## R0201-4k7
designator R?, comment 4k7
Resistor, ±1%, 0.05W; Part Number: R0201-4k7; Manufacturer: N.A.; Part number IPS: 00000001706; Part number NEMS: 100100061; Note: Chip Res 1%; Pad Count: 2; Component Status: Active
footprint RESC0603X03L_C
pins: 1, 2

## R0201-5k1
designator R?, comment 5k1
Resistor, ±1%, 0.05W; Part Number: R0201-5k1; Manufacturer: N.A.; Part number Norautron: 26192285; Part number NEMS: 100100565; Pad Count: 2; Note: Chip Res 1%; Component Status: Active
footprint RESC0603X03L_C
pins: 1, 2

## R0201-10k
designator R?, comment 10k
Resistor, ±1%, 0.05W; Part Number: R0201-10k; Manufacturer: N.A.; Part number IPS: 00000001255; Part number Norautron: 26107101; Part number NEMS: 100100065; Note: Chip Res 1%; Pad Count: 2; Component Status: Active
footprint RESC0603X03L_C
pins: 1, 2

## R0201-12k
designator R?, comment 12k
Resistor, ±1%, 0.05W; Part Number: R0201-12k; Manufacturer: N.A.; Part number IPS: 00000007891; Part number Norautron: 26192279; Part number NEMS: 100100066; Note: Chip Res 1%; Pad Count: 2; Component Status: Active
footprint RESC0603X03L_C
pins: 1, 2

## R0201-18k
designator R?, comment 18k
Resistor, ±1%, 0.05W; Part Number: R0201-18k; Manufacturer: N.A.; Part number IPS: 00000001707; Part number NEMS: 100100069; Note: Chip Res 1%; Pad Count: 2; Component Status: Active
footprint RESC0603X03L_C
pins: 1, 2

## R0201-47k
designator R?, comment 47k
Resistor, ±1%, 0.05W; Part Number: R0201-47k; Manufacturer: N.A.; Part number IPS: 00000001423; Part number NEMS: 100100076; Note: Chip Res 1%; Pad Count: 2; Component Status: Active
footprint RESC0603X03L_C
pins: 1, 2

## R0201-100k
designator R?, comment 100k
Resistor, ±1%, 0.05W; Part Number: R0201-100k; Manufacturer: N.A.; Part number IPS: 00000001419; Part number Norautron: 26108487; Part number NEMS: 100100080; Note: Chip Res 1%; Pad Count: 2; Component Status: Active
footprint RESC0603X03L_C
pins: 1, 2

## R0201-120
designator R?, comment 120R
Resistor, ±1%, 0.05W; Part Number: R0201-120; Manufacturer: N.A.; Part number IPS: 00000000880; Part number Norautron: 26107076; Part number NEMS: 100100028; Note: Chip Res 1%; Pad Count: 2; Component Status: Active
footprint RESC0603X03L_C
pins: 1, 2

## R0201-150
designator R?, comment 150R
Resistor, ±1%, 0.05W; Part Number: R0201-150; Manufacturer: N.A.; Part number IPS: 00000001420; Part number NEMS: 100100029; Note: Chip Res 1%; Pad Count: 2; Component Status: Active
footprint RESC0603X03L_C
pins: 1, 2

## R0201-150k
designator R?, comment 150k
Resistor, ±1%, 0.05W; Part Number: R0201-150k; Manufacturer: N.A.; Part number IPS: 00000001422; Part number NEMS: 100100082; Note: Chip Res 1%; Pad Count: 2; Component Status: Active
footprint RESC0603X03L_C
pins: 1, 2

## R0201-N.C.
designator R?, comment N.C.
Not mounted; Part Number: R0201-N.C.; Manufacturer: N.A.; Part number NEMS: 100100107; Note: Chip Res; Assembly: Not mounted; Pad Count: 2; Component Status: Active
footprint RESC0603X03L_C_NC
pins: 1, 2

## R0402-0R
designator R?, comment 0R
Resistor, ±5%, 0.063W; Part Number: R0402-0R; Manufacturer: N.A.; Part number IPS: 00000007128; Part number NEMS: 100100109; Note: Chip Res 5%; Artikkelnr Noca: 27049000; Pad Count: 2; Component Status: Active
footprint RESC1005X04L
pins: 1, 2

## R0402-N.C.
designator R?, comment N.C.
Not mounted; Part Number: R0402-N.C.; Manufacturer: N.A.; Part number NEMS: 100100281; Note: Chip Res; Assembly: Not mounted; Pad Count: 2; Component Status: Active
footprint RESC1005X04L_NC
pins: 1, 2

## RV2C010UNT2L
designator Q?
N-Channel MOSFET, 20V, 1A, 470mOhm, 400mW; Manufacturer: Rohm Semiconductor; Part number IPS: 00000009976; Part number Norautron: 26320026; Part number NEMS: 101300132; Note: N.A.; Artikkelnr Noca: 35010020; Pad Count: 3; Component Status: Active
footprint DFN65P100X40-3L
pins: 1 G, 2 S, 3 D

## SD-80259-1021
designator J?, comment USB-C 2.0
USB-C Receptacle, 16 Pin, USB 2.0; Part Number: SD-80259-1021; Manufacturer: Bellweather Electronic Corp.; Part number NEMS: 100500830; Pad Count: 16; Note: N.A.; Component Status: Active; System: Connector
footprint SD-80259-001
pins: A1 GND (power), A4 VBUS (power), A5 CC1, A6 DP1, A7 DN1, A8 SBU1, A9 VBUS (power), A12 GND (power), B5 CC2, B6 DP2, B7 DN2, B8 SBU2, SHLD SHELL (power)

## SHUNT JUMPER 2.54mm BLACK GOLD Horizontal (obsolete)
designator Y?, comment Shunt 2.54mm  Assembly: Placed on P30
Shunt Jumper 2.54mm Black; Part Number: SHUNT JUMPER 2.54mm BLACK GOLD Horizontal (Obsolete); Manufacturer: 3M; Manufacturer Part Number: 969102-0000-DA; Part number IPS: 00000001916; Part number Norautron: N.A.; Part number NEMS: 100500644; Note: SHUNT JUMPER .1" BLACK GOLD, h=6.00mm, w=5.00mm; Artikkelnr Noca: 56099001; Pad Count: 2; Component Status: Obsolete; System: Connector
footprint Shunt_2.54mm_Horizontal

## SKY65943-11
designator U?
GNSS Low-Noise Amplifier Front-End Module with Integrated Pre-Filter and Post-Filter; Manufacturer: Skyworks; Part number IPS: 00000002997; Part number NEMS: 101900584; Note: N.A.; Pad Count: 10; Component Status: Active
footprint SKY65943-11
pins: 1 GND (power), 2 VEN (in), 3 VCC (power), 4 GND (power), 5 RF_IN (in), 6 GND (power), 7 FIL_OUT (out), 8 AMP_IN (in), 9 GND (power), 10 RF_OUT (out), 11 GND (power)

## Socket 1x6 SMD
designator P?, comment Socket 1x6
Socket 1x6, 2.54mm (100mil), SMD; Part Number: Socket 1x6 SMD; Manufacturer: WCON; Manufacturer Part Number: 2171-106MS0CUNR1; Part number IPS: 00000009964; Part number Norautron: 26032370; Part number NEMS: 100500408; Note: N.A.; Artikkelnr Noca: 55030001; Pad Count: 6; Component Status: Active; System: Connector
footprint SOCKET_1x6_SMD
pins: 1, 2, 3, 4, 5, 6
1 alternate drawing of the same symbol

## Socket 1x8 SMD
designator P?, comment Socket 1x8
Socket 1x8, 2.54mm (100mil), SMD; Part Number: Socket 1x8 SMD; Manufacturer: WCON; Manufacturer Part Number: 2171-108MS0CUNR1; Part number IPS: 00000009963; Part number Norautron: 26032369; Part number NEMS: 100500412; Note: N.A.; Artikkelnr Noca: 55030002; Pad Count: 8; Component Status: Active; System: Connector
footprint SOCKET_1x8_SMD
pins: 1, 2, 3, 4, 5, 6, 7, 8
1 alternate drawing of the same symbol

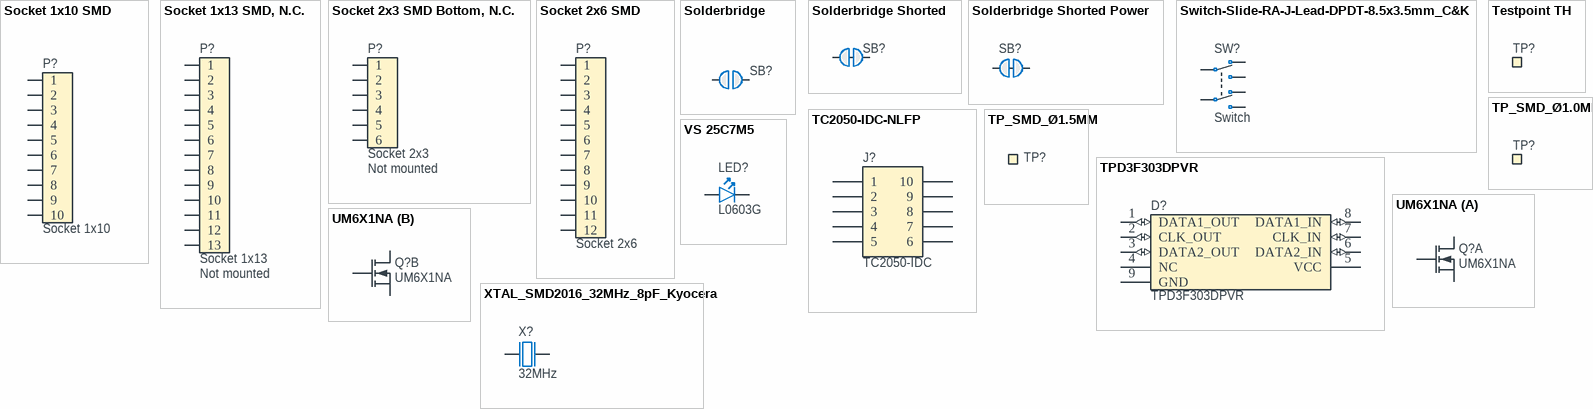
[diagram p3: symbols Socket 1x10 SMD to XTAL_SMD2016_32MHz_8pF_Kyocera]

## Socket 1x10 SMD
designator P?, comment Socket 1x10
Socket 1x10, 2.54mm (100mil), SMD; Part Number: Socket 1x10 SMD; Manufacturer: WCON; Manufacturer Part Number: 2171-110MS0CUNR1; Part number IPS: 00000009965; Part number Norautron: 26032371; Part number NEMS: 100500416; Note: N.A.; Artikkelnr Noca: 55030004; Pad Count: 10; Component Status: Active; System: Connector
footprint SOCKET_1x10_SMD
pins: 1, 2, 3, 4, 5, 6, 7, 8, 9, 10
1 alternate drawing of the same symbol

## Socket 1x13 SMD, N.C.
designator P?, comment Socket 1x13  Assembly: Not mounted
Socket 1x13, 2.54mm (100mil), SMD; Part Number: Socket 1x13 SMD, N.C.; Manufacturer: WCON; Manufacturer Part Number: 2171-113MS0CUNR1; Part number NEMS: 100500422; Note: N.A.; Pad Count: 13; Component Status: Active; System: Connector
footprint LIST_1x13_SMD-NC
pins: 1, 2, 3, 4, 5, 6, 7, 8, 9, 10, 11, 12, 13

## Socket 2x3 SMD Bottom, N.C.
designator P?, comment Socket 2x3  Assembly: Not mounted
Socket 2x3, 2.54mm (100mil), SMD; Part Number: Socket 2x3 SMD Bottom, N.C.; Manufacturer: WCON; Manufacturer Part Number: 2171-203MS0CUNR1; Part number NEMS: 100500434; Note: N.A.; Artikkelnr Noca: 55030010; Pad Count: 6; Component Status: Active; System: Connector
footprint SOCKET_2x3_SMD-2.54mm-bottom-NC
pins: 1, 2, 3, 4, 5, 6
1 alternate drawing of the same symbol

## Socket 2x6 SMD
designator P?, comment Socket 2x6
Socket 2x6, 2.54mm (100mil), SMD; Part Number: Socket 2x6 SMD; Manufacturer: WCON; Manufacturer Part Number: 2171-206MS0CUNR1; Part number NEMS: 100500439; Note: N.A.; Pad Count: 12; Component Status: Active; System: Connector
footprint SOCKET_2x6_SMD-2.54mm
pins: 1, 2, 3, 4, 5, 6, 7, 8, 9, 10, 11, 12
1 alternate drawing of the same symbol

## Solderbridge
designator SB?  (value not drawn)  (no BOM)
Manufacturer: N.A.; Part number NEMS: 100500458; Pad Count: 2; Component Status: Active; System: Connector
footprint Solderbridge
pins: 1 0, 2 1

## Solderbridge Shorted
designator SB?, comment Solderbridge  (value not drawn)  (net tie, no BOM)
Shorted Solderbridge; Part Number: Solderbridge Shorted; Manufacturer: N.A.; Part number NEMS: 100500459; Pad Count: 2; Component Status: Active; System: Connector
footprint Solderbridge_Shorted
pins: 1 0, 2 1

## Solderbridge Shorted Power
designator SB?, comment Solderbridge  (value not drawn)  (net tie, no BOM)
Shorted Solderbridge Power; Part Number: Solderbridge Shorted Power; Manufacturer: N.A.; Part number NEMS: 100500460; Pad Count: 2; Component Status: Active; System: Connector
footprint Solderbridge_Shorted_Power
pins: 1 0, 2 1

## Switch-Slide-RA-J-Lead-DPDT-8.5x3.5mm_C&K
designator SW?, comment Switch
SMD slide Switch (ON-ON); Part Number: Switch-Slide-RA-J-Lead-DPDT-8.5x3.5mm_C&K; Manufacturer: C&K; Manufacturer Part Number: JS202011JAQN; Part number IPS: 00000007811; Part number NEMS: 101500037; Note: N.A.; Pad Count: 6; Component Status: Active
footprint JS102011JAQN
pins: 1 N.O-1, 2 COM-1, 3 N.C-1, 4 N.O-2, 5 COM-2, 6 N.C-2

## TC2050-IDC-NLFP
designator J?, comment TC2050-IDC  (no BOM)
CBL PLUG-OF-NAILS 10-PIN; Part Number: TC2050-IDC-NLFP; Manufacturer: Tag-Connect LLC; Part number NEMS: 100500463; Artikkelnr Noca: N.A.; Pad Count: 10; Component Status: Active; System: Connector
footprint TC2050-IDC-NLFP
pins: 1, 2, 3, 4, 5, 6, 7, 8, 9, 10

## Testpoint TH
designator TP?, comment TP  (value not drawn)  (no BOM)
Testpoint, through hole; Part Number: Testpoint TH; Manufacturer: N.A.; Part number NEMS: 100500464; Pad Count: 1; Component Status: Active
footprint TESTPAD-TH
pins: 1

## TP_SMD_Ø1.0MM
designator TP?, comment Ø1.0mm,SMD  (value not drawn)  (no BOM)
1.0mm circular SMD testpad; Part Number: TP_SMD_Ø1.0MM; Manufacturer: Nordic Semiconductor; Manufacturer Part Number: N.A.; Part number NEMS: 100500475; Pad Count: 1; Component Status: Active
footprint TP_SMD_D1.0mm
pins: 1

## TP_SMD_Ø1.5MM
designator TP?, comment Ø1.5mm,SMD  (value not drawn)  (no BOM)
1.5mm circular SMD testpad; Part Number: TP_SMD_Ø1.5MM; Manufacturer: Nordic Semiconductor; Manufacturer Part Number: N.A.; Part number NEMS: 100500477; Pad Count: 1; Component Status: Active
footprint TP_SMD_D1.5mm
pins: 1

## TPD3F303DPVR
designator D?
ESD Protection and EMI Filter for SIM Card Interface; Manufacturer: Texas Instruments; Part number NEMS: 101900729; Note: N.A.; Pad Count: 8; Component Status: Active
footprint SON50P210X160X65_HS-9N
pins: 1 DATA1_OUT (io), 2 CLK_OUT (io), 3 DATA2_OUT (io), 4 NC, 5 VCC (power), 6 DATA2_IN (io), 7 CLK_IN (io), 8 DATA1_IN (io), 9 GND (power)

## UM6X1NA
designator Q?
Dual N-Channel MOSFET, Vds = 30V, Vgs(th) = 1.5V, Id = 0.5A, Rds = 750mOhm, Pd = 150mW; Manufacturer: Micro Commercial Components; Manufacturer Part Number: UM6X1NA-TP; Part number NEMS: 101300201; Note: N.A.; Pad Count: 6; Component Status: Active
footprint SOTFL50P162X60-6N
part A pins: 1 S1, 2 G1, 6 D1
part B pins: 3 D2, 4 S2, 5 G2

## VS 25C7M5
designator LED?, comment L0603G
LED, Green, 0603, 573nm, Vf=2.0V, 24mcd, - 40 to +85°C; Part Number: VS 25C7M5; Manufacturer: Victory Electronics; Part number IPS: 00000001274, 00000009961; Part number Norautron: 26313411; Part number NEMS: 101400097; Note: N.A.; Artikkelnr Noca: 13019193; Pad Count: 2; Component Status: Active
footprint LED_0603_G
pins: 1 C, 2 A

## XTAL_SMD2016_32MHz_8pF_Kyocera
designator X?, comment 32MHz
XTAL SMD 2016, 32MHz, Cl=8pF, Tot: ±40ppm; Part Number: XTAL_SMD2016_32MHz_8pF_Kyocera; Manufacturer: Kyocera; Manufacturer Part Number: CX2016DB32000D0WZRC1; Part number IPS: 00000007827; Part number Norautron: 26511136; Part number NEMS: 101600039; Pad Count: 4; Note: XTAL SMD 32.000MHz; Artikkelnr Noca: 22010022; Component Status: Active
footprint BT-XTAL_2016
pins: 1 inp, 2 GND hidden to GND, 3 out, 4 GND hidden to GND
